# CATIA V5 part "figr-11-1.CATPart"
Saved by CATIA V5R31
Part number: Part1
Bounding box of the stored display mesh (mm): x -50 to 50, y -98.731 to 72.975, z 0 to 120
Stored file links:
  D:\PROJECTS\Project 2021\US EDITION\CATIA V5 6R 2021\Resources\Part Files\c11_catia_v5_6r2021_prt\figr-11-1.CATPart
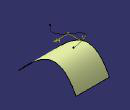
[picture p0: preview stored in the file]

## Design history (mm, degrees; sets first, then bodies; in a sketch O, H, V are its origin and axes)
Set1
  Sketch1 on yz-plane, origin (0, 0, 0), H (0, 1, 0), V (0, 0, 1)
    spline S1 through (-98.7309, 0) (-73.2816, 27.1192) (0, 74.8227) (72.975, 18.624)
    point P1 (-98.7309, 0)
    point P2 (0, 74.8227)
    coincidence: P1 H, P2 V
  Extrude1: Element1 Sketch1, Lim1 50, Lim2 50, Direction yz-plane
  Plane1: type Offset, RefPlane xy-plane, Offset 120
  Sketch2 on Plane1, origin (0, 0, 120), H (1, 0, 0), V (0, 1, 0)
    spline S1 through (28.7787, 44.6229) (-22.3035, 19.7059) (20.5049, -22.8447) (5.396, -48.9118)
Body1 (main body)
